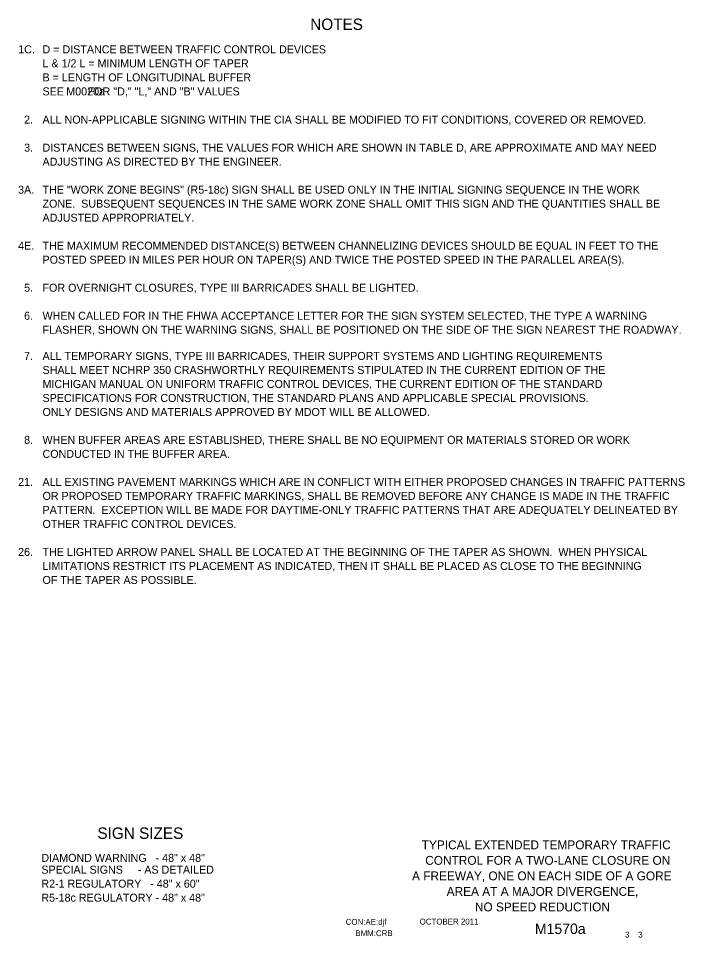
# Model space of a CAD drawing. Extents: x 16563 to 19504, y 6261 to 8279.
# Drawn here: x 18805 to 19504, y 7231 to 8195 of the extents above; entities that cross this region are included whole.
import ezdxf

# ---------------------------------------------------------------- set-up
doc = ezdxf.new("R2010")
doc.units = 0
for name, color, linetype in [('BORDER', 7, 'Continuous'), ('BORDER_SIGNAL_WO', 7, 'Continuous'), ('TYPICAL_TEXT_DIMEN_PR', 7, 'Continuous')]:
    doc.layers.add(name, color=color, linetype=linetype)

msp = doc.modelspace()

# ---------------------------------------------------------------- linework, layer by layer
at = {"layer": 'BORDER'}
for p, q in [((18959.08, 7346.77), (18959.08, 7346.77)), ((19347.25, 7297.5), (19347.25, 7297.5)), ((19347.25, 7297.5), (19347.25, 7297.5))]:
    msp.add_line(p, q, dxfattribs=at)

# ---------------------------------------------------------------- texts
for s, p in [('TYPICAL EXTENDED TEMPORARY TRAFFIC', (19228.5, 7323.57)), ('CONTROL FOR A TWO-LANE CLOSURE ON', (19232.14, 7307.27)), ('A FREEWAY, ONE ON EACH SIDE OF A GORE', (19218.3, 7290.97)), ('AREA AT A MAJOR DIVERGENCE,', (19254.61, 7274.67)), ('NO SPEED REDUCTION', (19284.23, 7258.37))]:
    msp.add_text(s, height=9.3, dxfattribs=at).set_placement(p)
at = {"layer": 'BORDER_SIGNAL_WO'}
for s, height, p in [('CON:AE:djf  ', 6.2, (19148.69, 7244.31)), ('    OCTOBER 2011    ', 6.2, (19217.08, 7244.59)), ('    M1570a   ', 11, (19330.86, 7234.63)), ('BMM:CRB   ', 6.2, (19158.81, 7232.42)), (' 3    3 ', 6.2, (19439.45, 7230.95))]:
    msp.add_text(s, height=height, dxfattribs=at).set_placement(p)
at = {"layer": 'TYPICAL_TEXT_DIMEN_PR'}
for s, height, p in [('NOTES', 12, (19111.55, 8183.25)), ('1C.', 8.4, (18805.19, 8158.72)), ('D = DISTANCE BETWEEN TRAFFIC CONTROL DEVICES', 8.4, (18830.7, 8158.72)), ('L & 1/2 L = MINIMUM LENGTH OF TAPER', 8.4, (18830.7, 8144.02)), ('B = LENGTH OF LONGITUDINAL BUFFER', 8.4, (18830.7, 8129.32)), ('SEE        FOR "D," "L," AND "B" VALUES', 8.4, (18830.7, 8114.62)), ('M0020a', 8.4, (18855.62, 8114.62)), ('2.', 8.4, (18811.39, 8085)), ('ALL NON-APPLICABLE SIGNING WITHIN THE CIA SHALL BE MODIFIED TO FIT CONDITIONS, COVERED OR REMOVED.', 8.4, (18830.7, 8085)), ('3.', 8.4, (18811.39, 8055.6)), ('DISTANCES BETWEEN SIGNS, THE VALUES FOR WHICH ARE SHOWN IN TABLE D, ARE APPROXIMATE AND MAY NEED', 8.4, (18830.7, 8055.6)), ('ADJUSTING AS DIRECTED BY THE ENGINEER.', 8.4, (18830.7, 8040.9)), ('3A.', 8.4, (18805.09, 8011.5)), ('THE "WORK ZONE BEGINS" (R5-18c) SIGN SHALL BE USED ONLY IN THE INITIAL SIGNING SEQUENCE IN THE WORK', 8.4, (18830.7, 8011.5)), ('ZONE.  SUBSEQUENT SEQUENCES IN THE SAME WORK ZONE SHALL OMIT THIS SIGN AND THE QUANTITIES SHALL BE', 8.4, (18830.7, 7996.8)), ('ADJUSTED APPROPRIATELY.', 8.4, (18830.7, 7982.1)), ('4E.', 8.4, (18805.13, 7952.7)), ('THE MAXIMUM RECOMMENDED DISTANCE(S) BETWEEN CHANNELIZING DEVICES SHOULD BE EQUAL IN FEET TO THE', 8.4, (18830.7, 7952.7)), ('POSTED SPEED IN MILES PER HOUR ON TAPER(S) AND TWICE THE POSTED SPEED IN THE PARALLEL AREA(S).', 8.4, (18830.7, 7938)), ('5.', 8.4, (18811.39, 7908.6)), ('FOR OVERNIGHT CLOSURES, TYPE III BARRICADES SHALL BE LIGHTED. ', 8.4, (18830.7, 7908.6)), ('6.', 8.4, (18811.34, 7879.2)), ('WHEN CALLED FOR IN THE FHWA ACCEPTANCE LETTER FOR THE SIGN SYSTEM SELECTED, THE TYPE A WARNING ', 8.4, (18830.7, 7879.2)), ('FLASHER, SHOWN ON THE WARNING SIGNS, SHALL BE POSITIONED ON THE SIDE OF THE SIGN NEAREST THE ROADWAY.', 8.4, (18830.7, 7864.5)), ('7.', 8.4, (18811.34, 7837)), ('ALL TEMPORARY SIGNS, TYPE III BARRICADES, THEIR SUPPORT SYSTEMS AND LIGHTING REQUIREMENTS', 8.4, (18830.7, 7837.02)), ('SHALL MEET NCHRP 350 CRASHWORTHLY REQUIREMENTS STIPULATED IN THE CURRENT EDITION OF THE', 8.4, (18830.7, 7822.32)), ('MICHIGAN MANUAL ON UNIFORM TRAFFIC CONTROL DEVICES, THE CURRENT EDITION OF THE STANDARD', 8.4, (18830.7, 7807.62)), ('SPECIFICATIONS FOR CONSTRUCTION, THE STANDARD PLANS AND APPLICABLE SPECIAL PROVISIONS.', 8.4, (18830.7, 7792.92)), ('ONLY DESIGNS AND MATERIALS APPROVED BY MDOT WILL BE ALLOWED.', 8.4, (18830.7, 7778.22)), ('8.', 8.4, (18811.39, 7748.95)), ('WHEN BUFFER AREAS ARE ESTABLISHED, THERE SHALL BE NO EQUIPMENT OR MATERIALS STORED OR WORK     ', 8.4, (18830.7, 7748.95)), ('CONDUCTED IN THE BUFFER AREA.', 8.4, (18830.7, 7734.25)), ('21.', 8.4, (18805.14, 7704.85)), ('ALL EXISTING PAVEMENT MARKINGS WHICH ARE IN CONFLICT WITH EITHER PROPOSED CHANGES IN TRAFFIC PATTERNS', 8.4, (18830.7, 7704.85)), ('OR PROPOSED TEMPORARY TRAFFIC MARKINGS, SHALL BE REMOVED BEFORE ANY CHANGE IS MADE IN THE TRAFFIC', 8.4, (18830.7, 7690.15)), ('PATTERN.  EXCEPTION WILL BE MADE FOR DAYTIME-ONLY TRAFFIC PATTERNS THAT ARE ADEQUATELY DELINEATED BY', 8.4, (18830.7, 7675.45)), ('OTHER TRAFFIC CONTROL DEVICES.', 8.4, (18830.7, 7660.75)), ('26.', 8.4, (18805.09, 7631.35)), ('THE LIGHTED ARROW PANEL SHALL BE LOCATED AT THE BEGINNING OF THE TAPER AS SHOWN.  WHEN PHYSICAL', 8.4, (18830.7, 7631.35)), ('LIMITATIONS RESTRICT ITS PLACEMENT AS INDICATED, THEN IT SHALL BE PLACED AS CLOSE TO THE BEGINNING', 8.4, (18830.7, 7616.65)), ('OF THE TAPER AS POSSIBLE.', 8.4, (18830.7, 7601.95)), ('SIGN SIZES', 12, (18888.3, 7334.46)), ('DIAMOND WARNING   - 48" x 48"', 8.4, (18829.48, 7310.37)), ('SPECIAL SIGNS     - AS DETAILED', 8.4, (18829.48, 7297.97)), ('R2-1 REGULATORY   - 48" x 60"', 8.4, (18829.48, 7283.27)), ('R5-18c REGULATORY - 48" x 48"', 8.4, (18829.48, 7268.57))]:
    msp.add_text(s, height=height, dxfattribs=at).set_placement(p)

doc.saveas('drawing.dxf')
